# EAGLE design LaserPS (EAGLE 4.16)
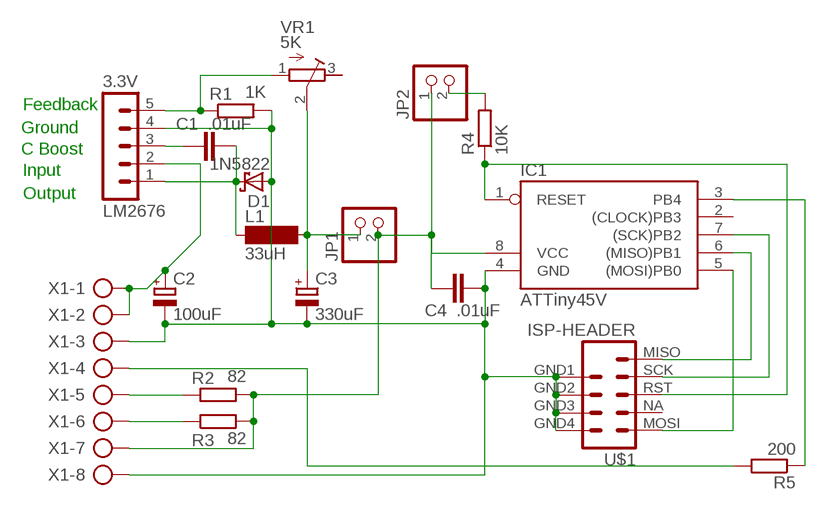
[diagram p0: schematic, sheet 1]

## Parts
3.3V  LM2676  MA05-1  [MA05-1]
C1  .01uF  C-EU025-024X044  [C025-024X044]
C2  100uF  CPOL-EUE3.5-10  [E3,5-10]
C3  330uF  CPOL-EUE3.5-10  [E3,5-10]
C4  .01uF  C-EU025-024X044  [C025-024X044]
D1  1N5822  1N5908  [C4111-15]
IC1  ATTiny45V  TINY22P  [DIL08]
JP1  PINHD-1X2  [1X02]
JP2  PINHD-1X2  [1X02]
L1  33uH  BS11  [BS11]
R1  1K  R-EU_0207/10  [0207/10]
R2  82  R-EU_0207/10  [0207/10]
R3  82  R-EU_0207/10  [0207/10]
R4  10K  R-EU_0207/10  [0207/10]
R5  200  R-EU_0207/10  [0207/10]
U$1  ISP-HEADER  [ISP-HEADER]
VR1  5K  R-TRIMM3339P  [RTRIM3339P]
X1  AK500/8  [AK500/8]

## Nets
N$1: 3.3V.2 C2.+ X1.1 X1.2
N$2: C4.1 IC1.8(VCC) JP1.2 JP2.1 R2.2 R3.2 X1.7
N$3: 3.3V.1 C1.2 D1.C L1.1
N$4: 3.3V.3 C1.1
N$5: C3.+ JP1.1 L1.2 VR1.2(S)
N$6: 3.3V.5 R1.1 VR1.1(E)
N$7: JP2.2 R4.2
N$8: IC1.6((MISO)PB1) U$1.MISO
N$9: IC1.7((SCK)PB2) U$1.SCK
N$10: IC1.5((MOSI)PB0) U$1.MOSI
N$11: IC1.1(RESET) R4.1 U$1.RST(RESET)
N$12: IC1.3(PB4) R5.1
N$13: R5.2 X1.4
N$14: 3.3V.4 C2.- C3.- C4.2 D1.A IC1.4(GND) R1.2 U$1.GND1 U$1.GND2 U$1.GND3 U$1.GND4 X1.3 X1.8
N$15: R2.1 X1.5
N$16: R3.1 X1.6
Unconnected: IC1.2((CLOCK)PB3) U$1.NA VR1.3(A)

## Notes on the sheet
- Feedback
- Ground
- C Boost
- Input
- Output

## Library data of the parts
3.3V = con-lstb:MA05-1: PIN HEADER
C1 C4 = rcl:C-EU: CAPACITOR, European symbol
C2 C3 = rcl:CPOL-EU: POLARIZED CAPACITOR, European symbol
D1 = diode:1N5908: DIODE
IC1 = atmel:TINY22: MICROCONTROLLER 1K ROM 128 bytes RAM 128 bytes EEPROM
JP1 JP2 = pinhead:PINHD-1X2: PIN HEADER
L1 = inductor-neosid:BS: INDUCTOR
R1-R5 = rcl:R-EU_: RESISTOR, European symbol
U$1 = Williams:ISP-HEADER
VR1 = rcl:R-TRIMM: Trimm resistor
X1 = con-ptr500:AK500/8: CONNECTOR

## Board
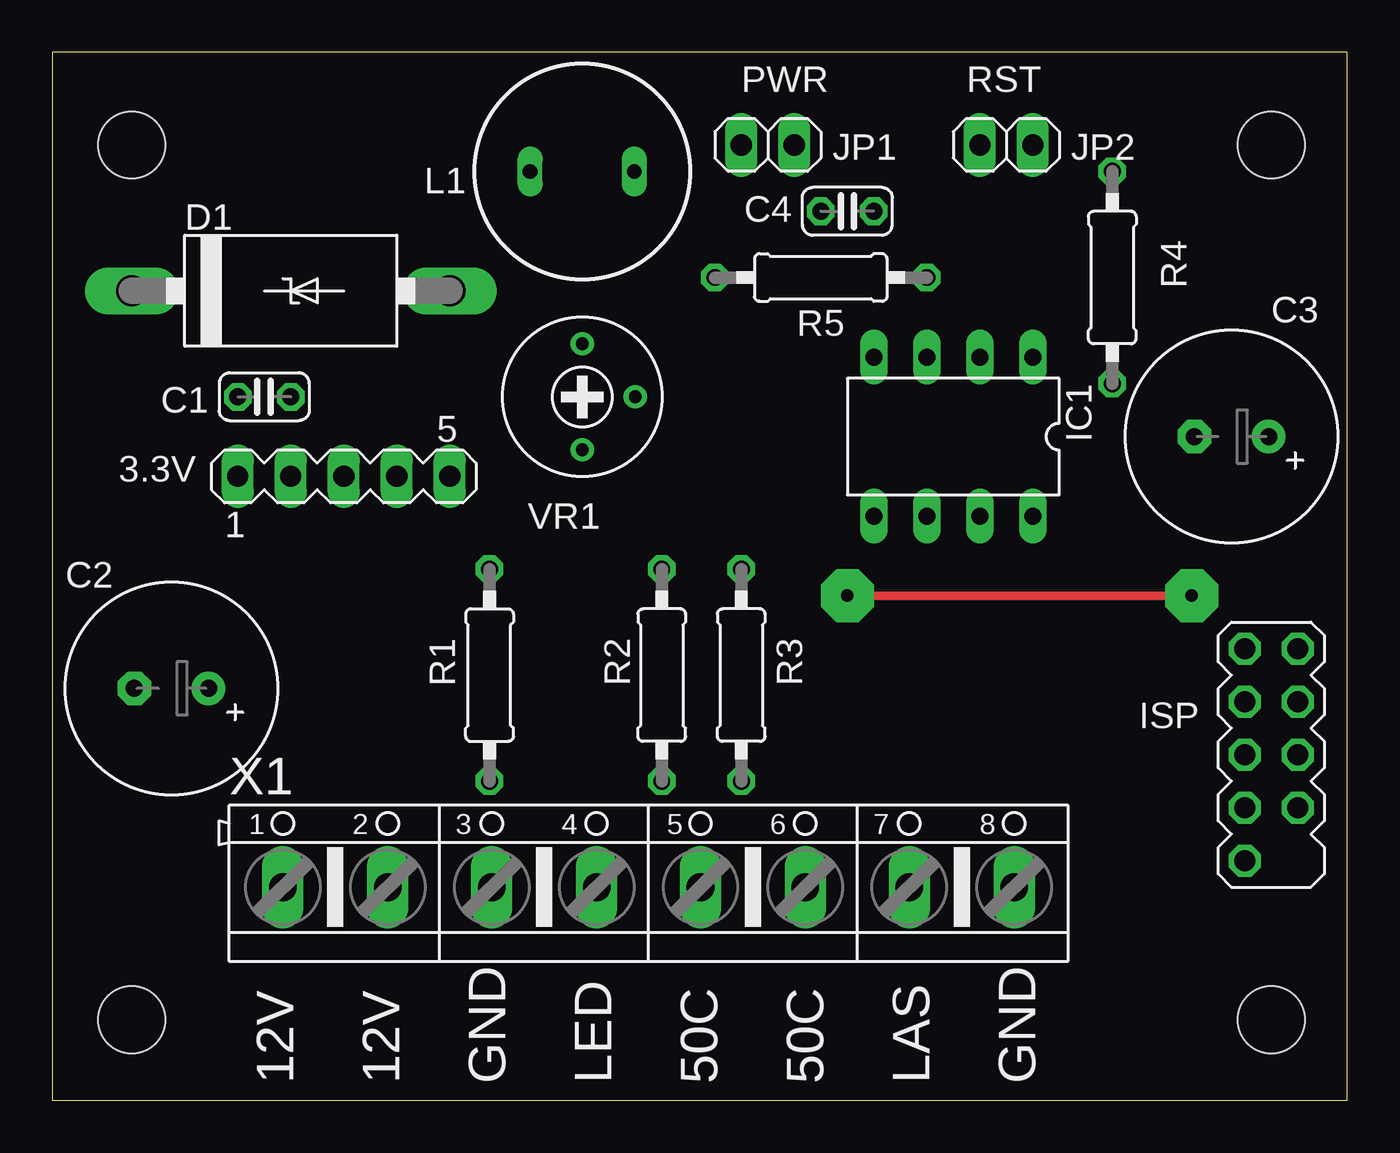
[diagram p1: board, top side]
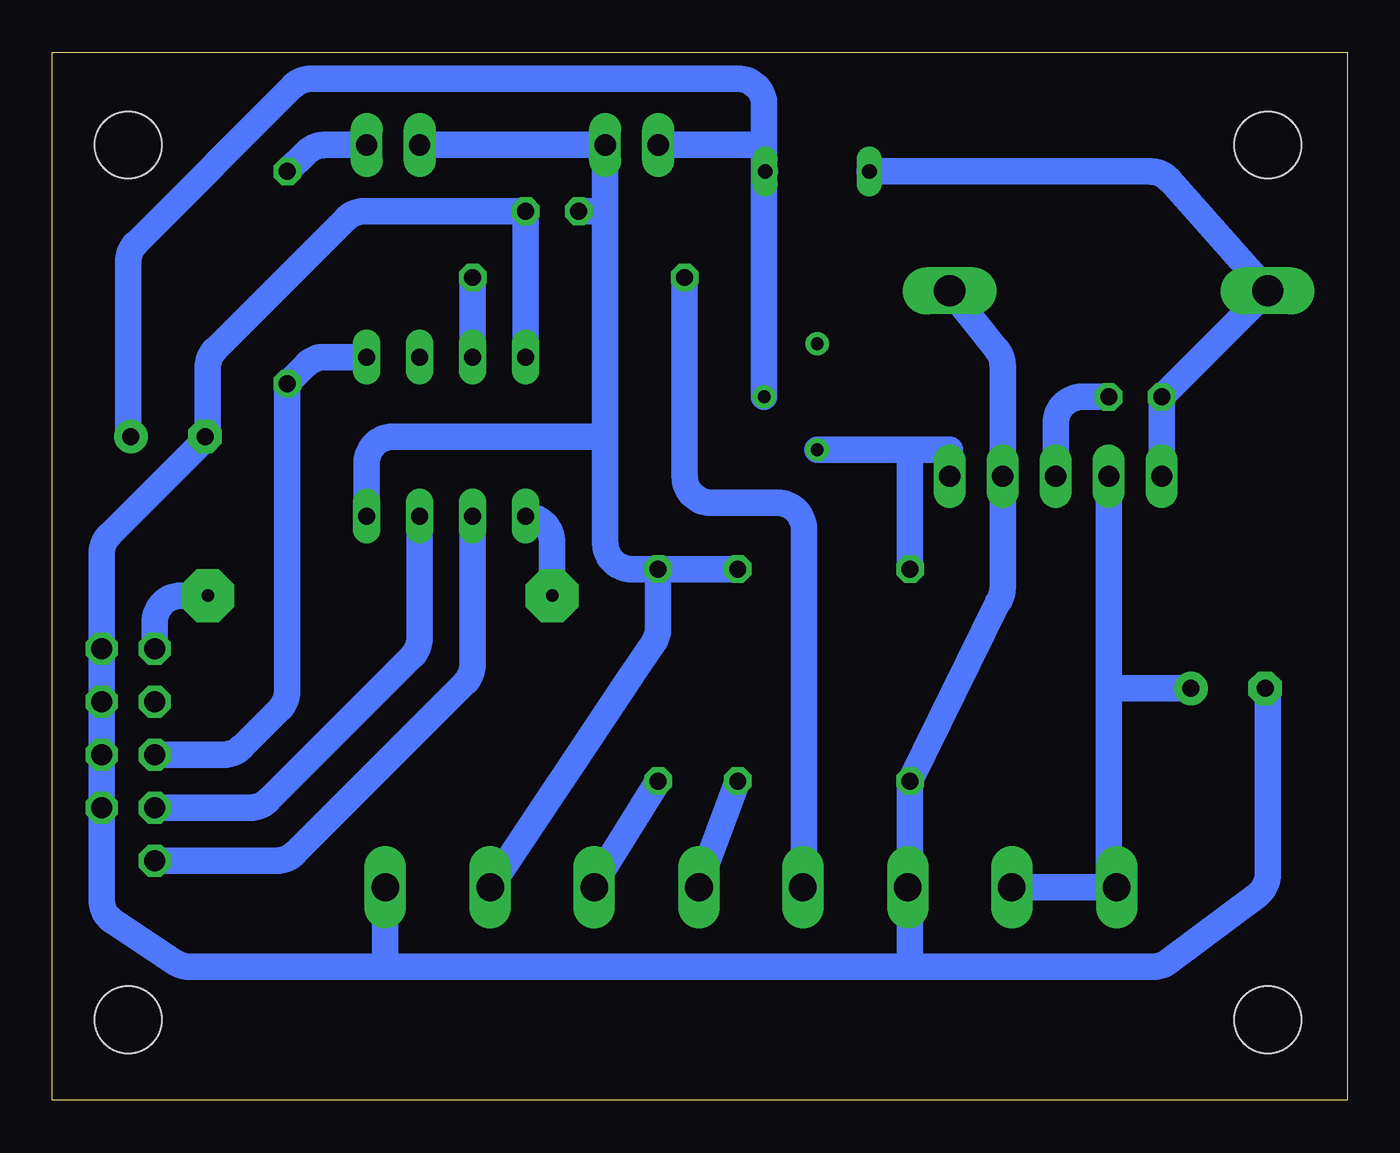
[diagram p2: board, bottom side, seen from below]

Size 62.07 x 50.21 mm. Coordinates in mm from the lower left corner, seen from the top.
Outline: 0,0 62.07,0 62.07,50.21 0,50.21 0,0
Copper layers (1*16): Top 0.035mm / dielectric 1.5mm / Bottom 0.035mm
Design rules "default": minimum track width 10mil, minimum drill 24mil, track to track 8mil, track to pad 8mil, pad to pad 8mil, via to via 8mil, smd to smd 8mil, copper to edge 40mil, drill to drill 8mil, minimum pad ring 10mil, minimum via ring 8mil, stop-mask expansion 4mil, vias tented up to drill 0mil, thermal gap 10mil
Holes 3.2 mm at 3.82,3.86 58.43,3.86 3.82,45.77 58.43,45.77
tRestrict: area 0.6,0.7 to 7,7; area 55.3,0.7 to 61.6,7; area 55.3,42.6 to 61.6,48.9; area 0.6,42.6 to 7,48.9

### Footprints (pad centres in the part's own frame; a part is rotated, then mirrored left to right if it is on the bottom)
MA05-1 = drill 1.016 long: 1 -5.08,0; 2 -2.54,0; 3 0,0; 4 2.54,0; 5 5.08,0
C025-024X044 = drill 0.813 octagon: 1 -1.27,0; 2 1.27,0
E3,5-10 = drill 0.813 pad 1.6 round: + -1.778,0 | drill 0.813 pad 1.6 octagon: - 1.778,0
C4111-15 = drill 1.499 long: A 7.62,0; C -7.62,0
DIL08 = drill 0.813 long: 1 -3.81,-3.81; 2 -1.27,-3.81; 3 1.27,-3.81; 4 3.81,-3.81; 5 3.81,3.81; 6 1.27,3.81; 7 -1.27,3.81; 8 -3.81,3.81
1X02 = drill 1.016 long: 1 -1.27,0; 2 1.27,0
BS11 = drill 0.7 long: 1 -2.5,0; 2 2.5,0
0207/10 = drill 0.813 octagon: 1 -5.08,0; 2 5.08,0
ISP-HEADER = drill 1.016 octagon: GND1 -2.54,-1.27; GND2 0,-1.27; GND3 2.54,-1.27; GND4 5.08,-1.27; MISO -5.08,1.27; MOSI 5.08,1.27; NA 2.54,1.27; RST 0,1.27; SCK -2.54,1.27
RTRIM3339P = drill 0.61 round: 1 -2.54,0; 2 0,-2.54; 3 2.54,0
AK500/8 = drill 1.321 long: 1 -17.526,0; 2 -12.497,0; 3 -7.518,0; 4 -2.489,0; 5 2.489,0; 6 7.518,0; 7 12.497,0; 8 17.526,0

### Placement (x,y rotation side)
3.3V  13.98,29.89 0 top
C1  10.17,33.7 180 top
C2  5.72,19.73 180 top
C3  56.52,31.8 180 top
C4  38.11,42.59 0 top
D1  11.44,38.78 0 top
IC1  43.19,31.8 180 top
JP1  34.3,45.77 0 top
JP2  45.73,45.77 0 top
L1  25.41,44.5 0 top
R1  20.96,20.37 270 top
R2  29.22,20.37 90 top
R3  33.03,20.37 90 top
R4  50.81,39.42 90 top
R5  36.84,39.42 180 top
U$1  58.43,16.56 90 top
VR1  25.41,33.7 90 top
X1  28.58,10.21 0 top

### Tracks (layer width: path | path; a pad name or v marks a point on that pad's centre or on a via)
N$1
  Bottom 0.406: X1.1 10.8,10.21 | X1.2 16.52,10.21
  Bottom 1.27: 11.44,10.21 X1.2 | X1.1 11.44,10.21 | 11.44,10.21 11.44,19.73 | 11.44,19.73 3.3V.2 | 11.44,19.73 C2.+
N$2
  Bottom 0.406: X1.7 41.09,10.21
  Bottom 1.27: 35.57,31.8 45.73,31.8 arc-90 47,30.53 IC1.8 | 35.57,31.8 35.57,42.59 | JP2.1 JP1.2 35.57,42.59 | R3.2 R2.2 | 41.09,10.21 34.3,20.37 33.24,21.95 arc-34 33.03,22.66 R3.2 | R3.2 34.3,25.45 arc90 35.57,26.72 35.57,31.8 | 35.57,42.59 C4.1
N$3
  Bottom 1.27: 3.3V.1 C1.2 D1.C 8.52,44.07 arc-48 9.47,44.5 L1.1
N$4
  Bottom 1.27: 3.3V.3 13.98,32.43 arc90 12.71,33.7 C1.1
N$5
  Bottom 1.27: VR1.2 27.95,44.5 | C3.+ 58.43,31.8 58.43,40.16 arc45 58.05,41.06 50.54,48.57 arc45 49.64,48.94 29.22,48.94 arc90 27.95,47.67 27.95,45.77 | 27.95,44.5 L1.2 | 27.95,44.5 27.95,45.77 | 27.95,45.77 JP1.1
N$6
  Bottom 1.27: 20.96,31.16 19.06,31.16 3.3V.5 | 20.96,31.16 VR1.1 | R1.1 20.96,31.16
N$7
  Bottom 1.27: R4.2 49.91,45.4 arc45 49.01,45.77 JP2.2
N$8
  Bottom 1.27: U$1.MISO 51.33,11.48 arc-45 50.43,11.85 42.29,20 arc-45 41.92,20.89 IC1.6
N$9
  Bottom 1.27: U$1.SCK 52.6,14.02 arc-45 51.7,14.39 44.83,21.27 arc-45 44.46,22.16 IC1.7
N$10  (via drill 0.6 pad 2.54)
  Top 0.406: v38.11,24.18 v54.62,24.18
  Bottom 1.27: IC1.5 arc90 38.11,26.72 v38.11,24.18 | v54.62,24.18 55.89,24.18 arc-90 57.16,22.91 U$1.MOSI
N$11
  Bottom 1.27: IC1.1 49.01,35.61 arc-45 49.91,35.24 R4.1 50.81,19.62 arc45 51.18,18.73 52.97,16.93 arc45 53.87,16.56 U$1.RST
N$12
  Bottom 1.27: IC1.3 R5.1
N$13
  Bottom 1.27: R5.2 31.76,29.89 arc-90 30.49,28.62 27.31,28.62 arc90 26.04,27.35 26.04,10.21 X1.4
N$14
  Bottom 0.406: 20.96,10.21 X1.3
  Bottom 1.27: 20.96,6.4 46.11,6.4 | 46.11,6.4 46.17,6.4 55.5,6.4 arc34 56.21,6.61 59.13,8.56 arc56 59.7,9.62 U$1.GND1 U$1.GND2 U$1.GND3 U$1.GND4 59.7,26.19 arc45 59.32,27.09 54.62,31.8 | 20.96,6.4 20.96,10.21 R1.2 16.75,23.85 arc-35 16.52,24.58 16.52,29.26 | 16.52,29.26 3.3V.4 | 46.11,6.4 X1.8 | 16.52,29.26 16.52,35.16 arc-39 16.79,35.96 D1.A | IC1.4 C4.2 47.1,42.59 arc-45 48,42.22 54.24,35.98 arc-45 54.62,35.08 54.62,31.8 | 20.96,6.4 9.32,6.4 arc-37 8.56,6.65 4.32,9.83 arc-53 3.82,10.84 3.82,19.73 C2.- | 54.62,31.8 C3.-
N$15
  Bottom 1.27: R2.1 31.12,10.21 X1.5
N$16
  Bottom 1.27: R3.1 36.2,10.21 X1.6

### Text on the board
tPlace: PWR | RST | ISP | 12V | 12V | GND | LED | 50C | 50C | LAS | GND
